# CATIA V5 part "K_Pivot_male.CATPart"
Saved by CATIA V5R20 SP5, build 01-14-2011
Part number: pivot_male
Bounding box of the stored display mesh (mm): x 0 to 32, y -30 to 30, z -40 to 40
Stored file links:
  G:\Khaled_CFAO_2011\ST2M\ST2M_GR1\lpierredon\Khaled\CAD_thinkMOTION\K_Pivot_male.CATPart
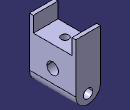
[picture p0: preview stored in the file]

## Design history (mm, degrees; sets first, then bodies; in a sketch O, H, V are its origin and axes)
Body1 (main body)
  Sketch1 on yz-plane, origin (0, 0, 0), H (0, 1, 0), V (0, 0, 1)
    line L1 (-30, 40) -> (-25, 40)
    line L2 (30, 40) -> (30, -40)
    line L3 (30, -40) -> (-30, -40)
    line L4 (-30, -40) -> (-30, 40)
    line L5 (-25, 40) -> (-25, 20)
    line L6 (-25, 20) -> (25, 20)
    line L7 (25, 20) -> (25, 40)
    point P8 (25, 40)
    line L8 (25, 40) -> (30, 40)
    length L3 = 60
    length L2 = 80
    length L6 = 50
    length L7 = 20
    horizontal: L1 H, L3 H, L6 H, L8 H
    vertical: L2 V, L4 V, L5 V, L7 V
    symmetry: L2 L4 V, L1 L3 H, L7 L5 V
    coincidence: P8 L1, L1 L8
  Pad1: profile Sketch1, direction (1, 0, 0), length 32
  Fillet1: radius 16, on edge [face of Pad1 from Sketch1.L3 | end face of Pad1]; edge [start face of Pad1 | face of Pad1 from Sketch1.L3]
  Sketch2 on zx-plane, origin (0, 0, 0), H (-1, 0, 0), V (0, 0, 1)
    circle A1 centre (-16, -28) radius 6
    point P1 (-16, -28)
    reference projected line E1 (0, -40) -> (0, 40) from edge [start face of Pad1 | face of Pad1 from Sketch1.L2]
    reference projected line E2 (-32, -40) -> (-32, 40) from edge [face of Pad1 from Sketch1.L2 | end face of Pad1]
    radius A1 = 6
    equidistance: E1 E2 P1
  Pocket1: profile Sketch2, direction (0, -1, 0), length 32, mirrored extent
  Sketch3 on yz-plane, origin (0, 0, 0), H (0, 1, 0), V (0, 0, 1)
    point P1 (0, 16)
    circle A1 centre (0, -7) radius 7.5
    point P2 (0, -7)
    reference projected line E1 through (0, -28) direction (1, 0) from axis of face of Pocket1 from Sketch2.A1
    radius A1 = 7.5
    distance E1 P2 = 21
    coincidence: P1 V, P2 V
  Pocket2: profile Sketch3, direction (1, 0, 0), length 32
  Sketch4 on face of Pad1 from Sketch1.L6, origin (12.2814, -2.4944, 20), H (1, 0, 0), V (0, 1, 0)
    point P1 (3.7186, 2.4944)
    reference projected line E1 (19.7186, 27.4944) -> (19.7186, -22.5056) from edge [face of Pad1 from Sketch1.L6 | end face of Pad1]
    reference projected line E2 (-12.2814, 27.4944) -> (-12.2814, -22.5056) from edge [start face of Pad1 | face of Pad1 from Sketch1.L6]
    reference projected line E3 (-12.2814, 27.4944) -> (19.7186, 27.4944) from edge [face of Pad1 from Sketch1.L7 | face of Pad1 from Sketch1.L8]
    reference projected line E4 (-12.2814, -22.5056) -> (19.7186, -22.5056) from edge [face of Pad1 from Sketch1.L1 | face of Pad1 from Sketch1.L5]
    equidistance: E1 E2 P1, E3 E4 P1
  Hole1: placed by Sketch4, at (16, 0, 20) direction (0, 0, -1), diameter 10, depth 10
